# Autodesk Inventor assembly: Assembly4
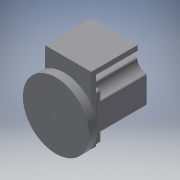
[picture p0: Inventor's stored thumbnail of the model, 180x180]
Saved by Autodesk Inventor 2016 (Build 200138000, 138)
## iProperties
Created: 2016-02
Part Number: Assembly4
Document SubType Name: Assembly
Designer: Juha-Pekka
Author: Juha-Pekka
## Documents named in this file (3)
- C:\Users\Juha-Pekka\Desktop\Assignment2\Assembly4.iam
- C:\Users\Juha-Pekka\Desktop\Assignment2\Assembly3.iam
- C:\Users\Juha-Pekka\Desktop\Assignment2\kiekko.ipt
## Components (2 placed, 2 different names)
1. Assembly3:1 [sub-assembly]
2. kiekko:1
